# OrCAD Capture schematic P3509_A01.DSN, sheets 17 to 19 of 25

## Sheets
17 0008_PRE-REG 5V: size Custom
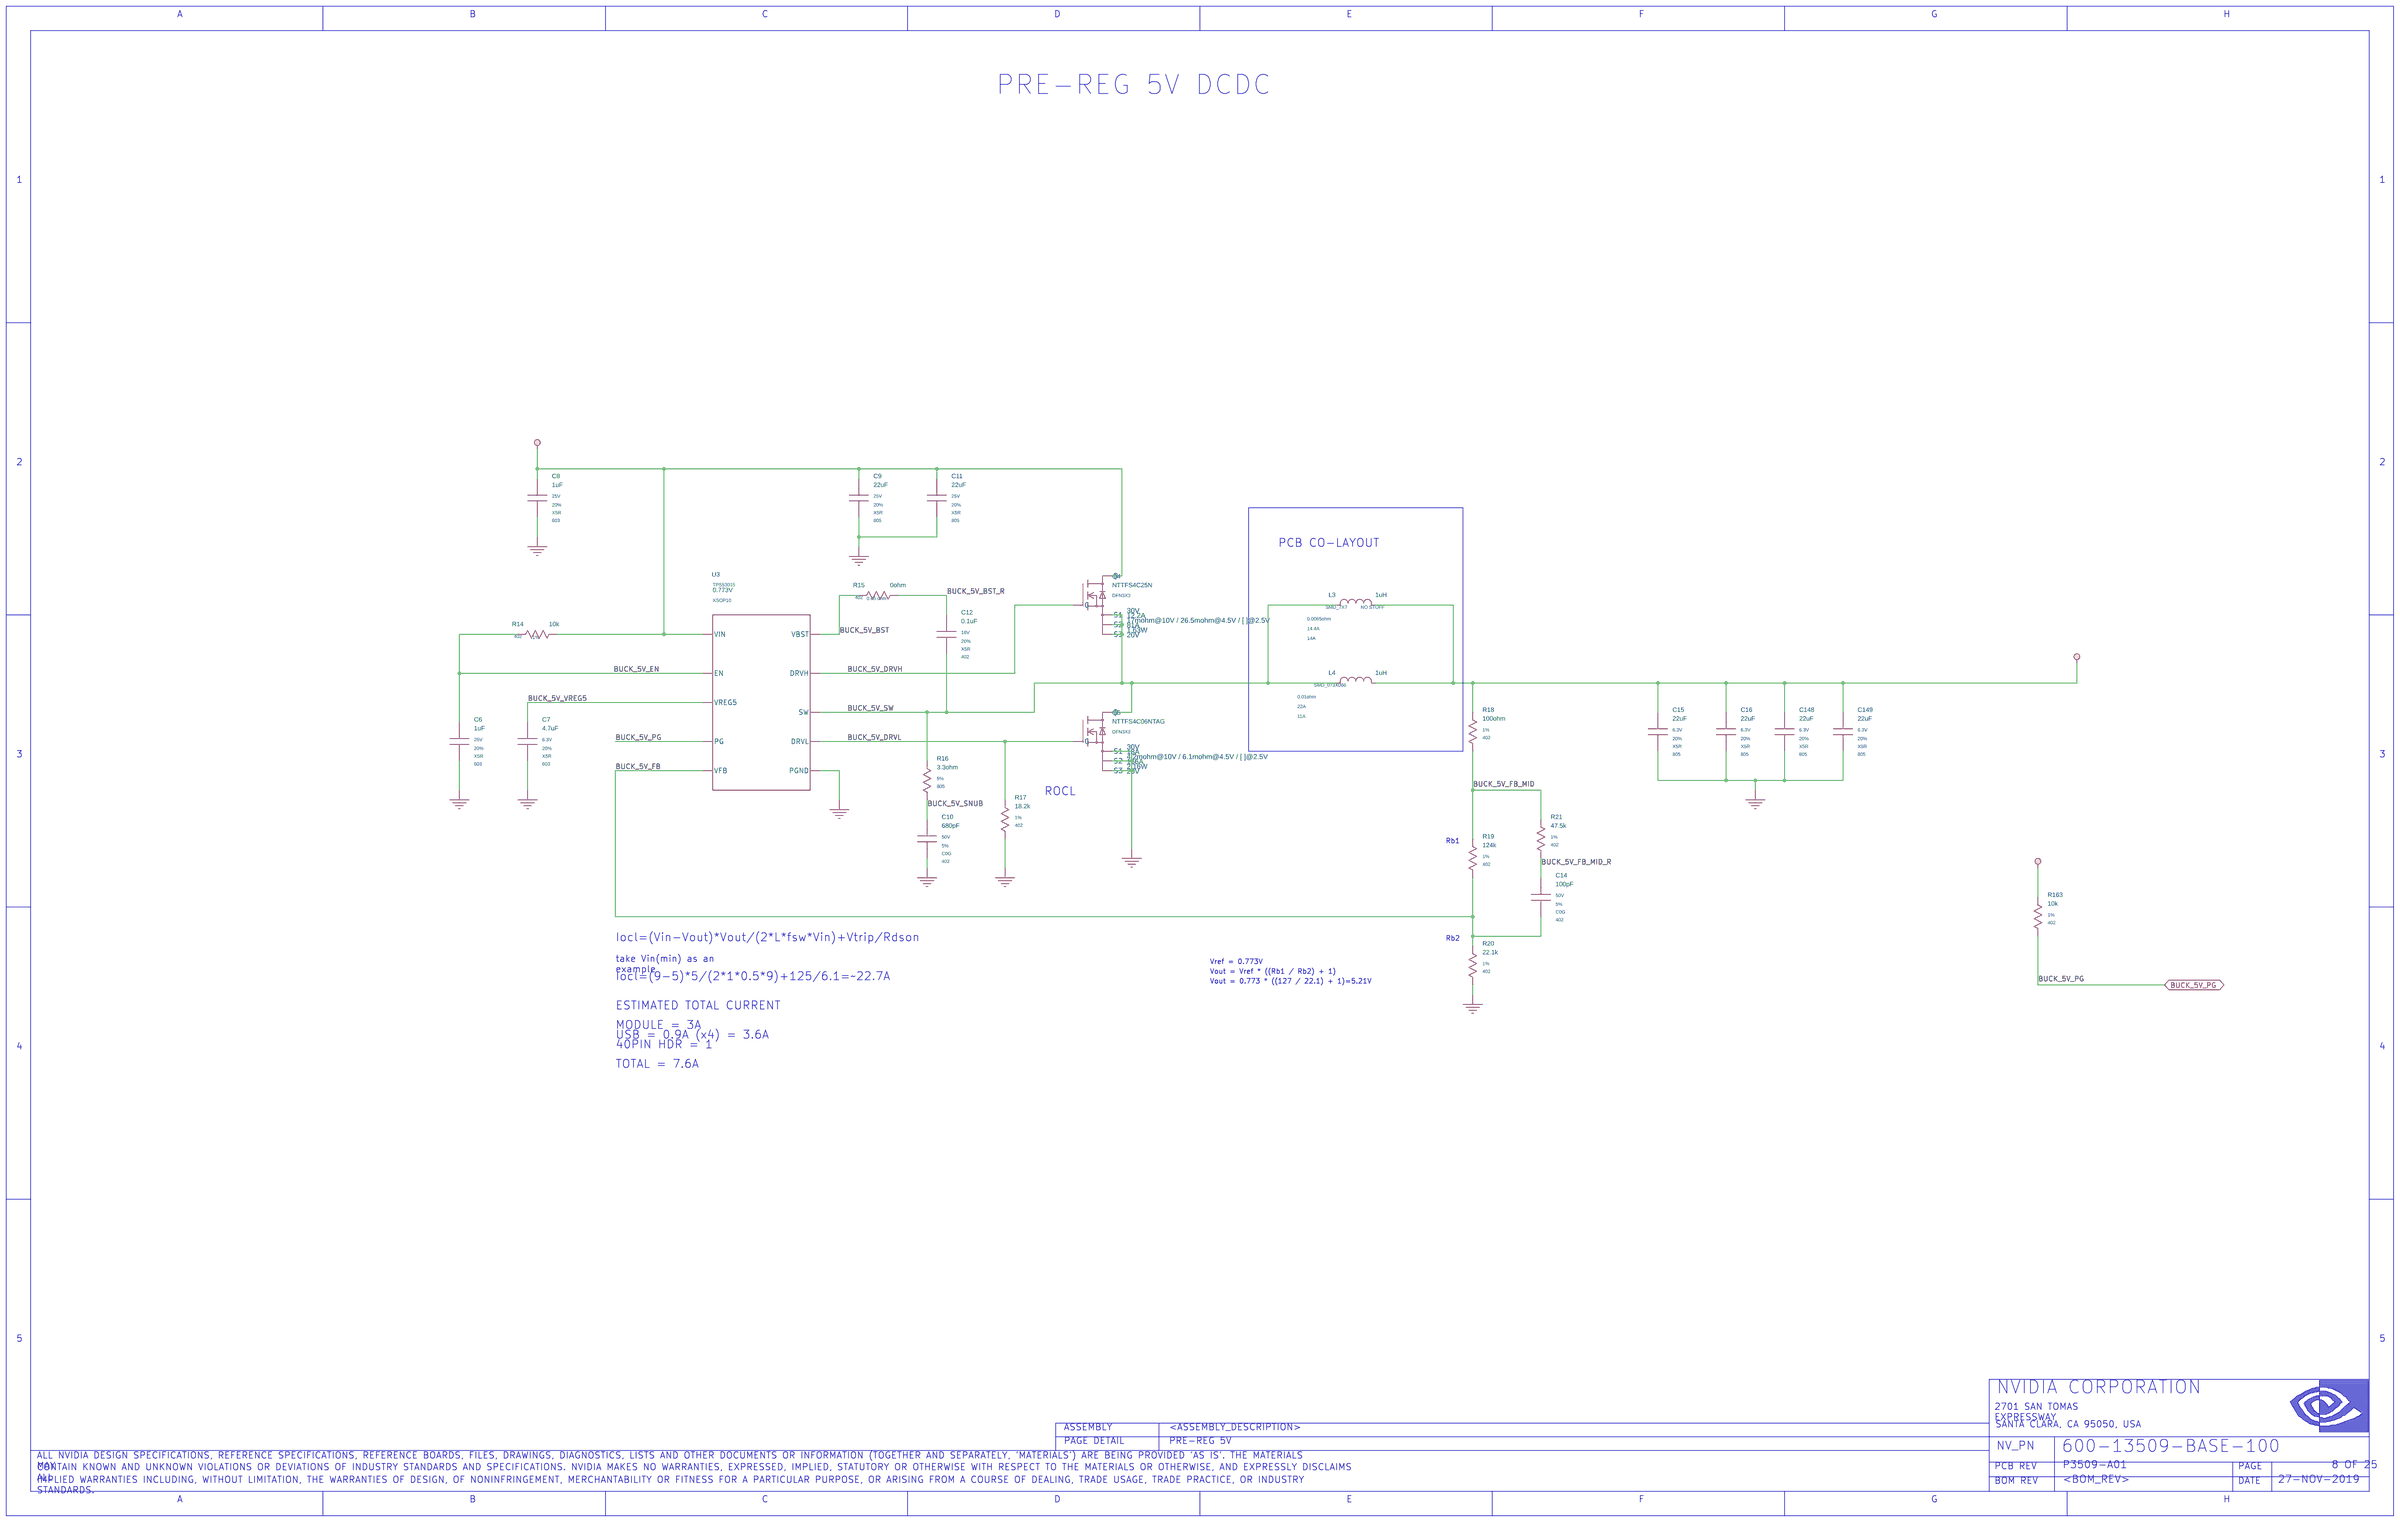
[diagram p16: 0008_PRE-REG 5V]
18 0007_DC_JACK: size Custom
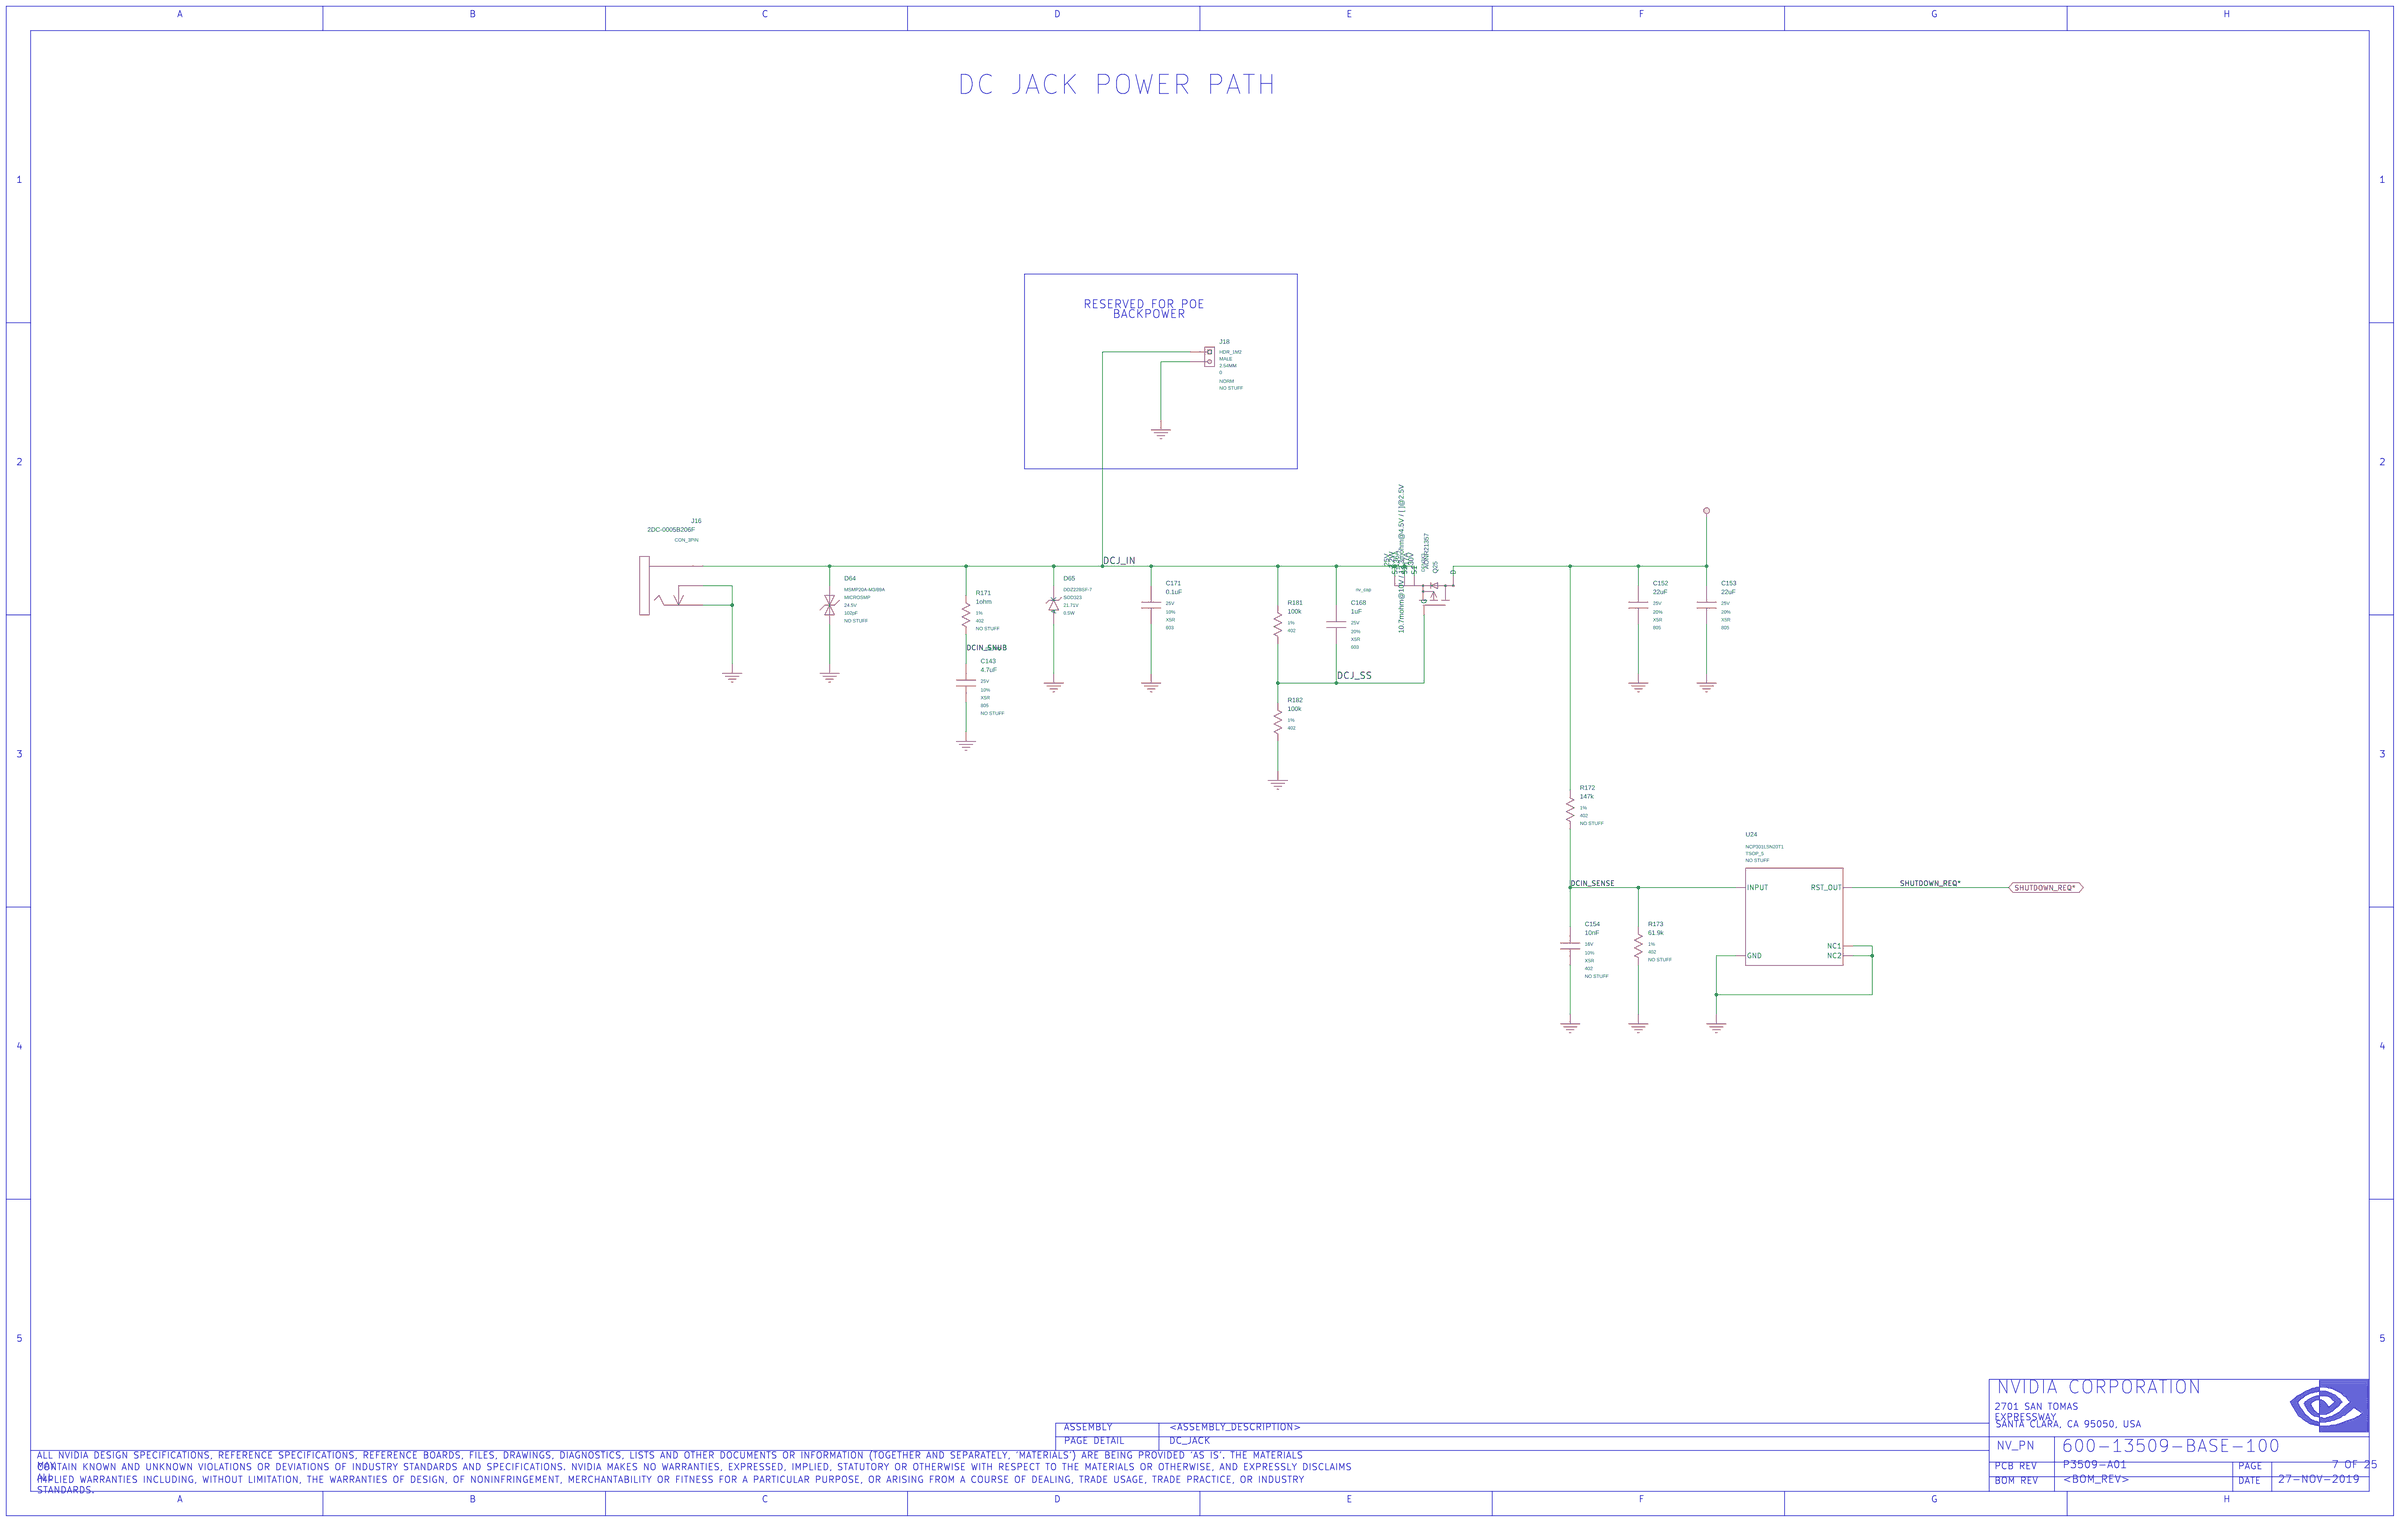
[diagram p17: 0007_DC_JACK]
19 0006_SODIMM Connector 3_3: size Custom
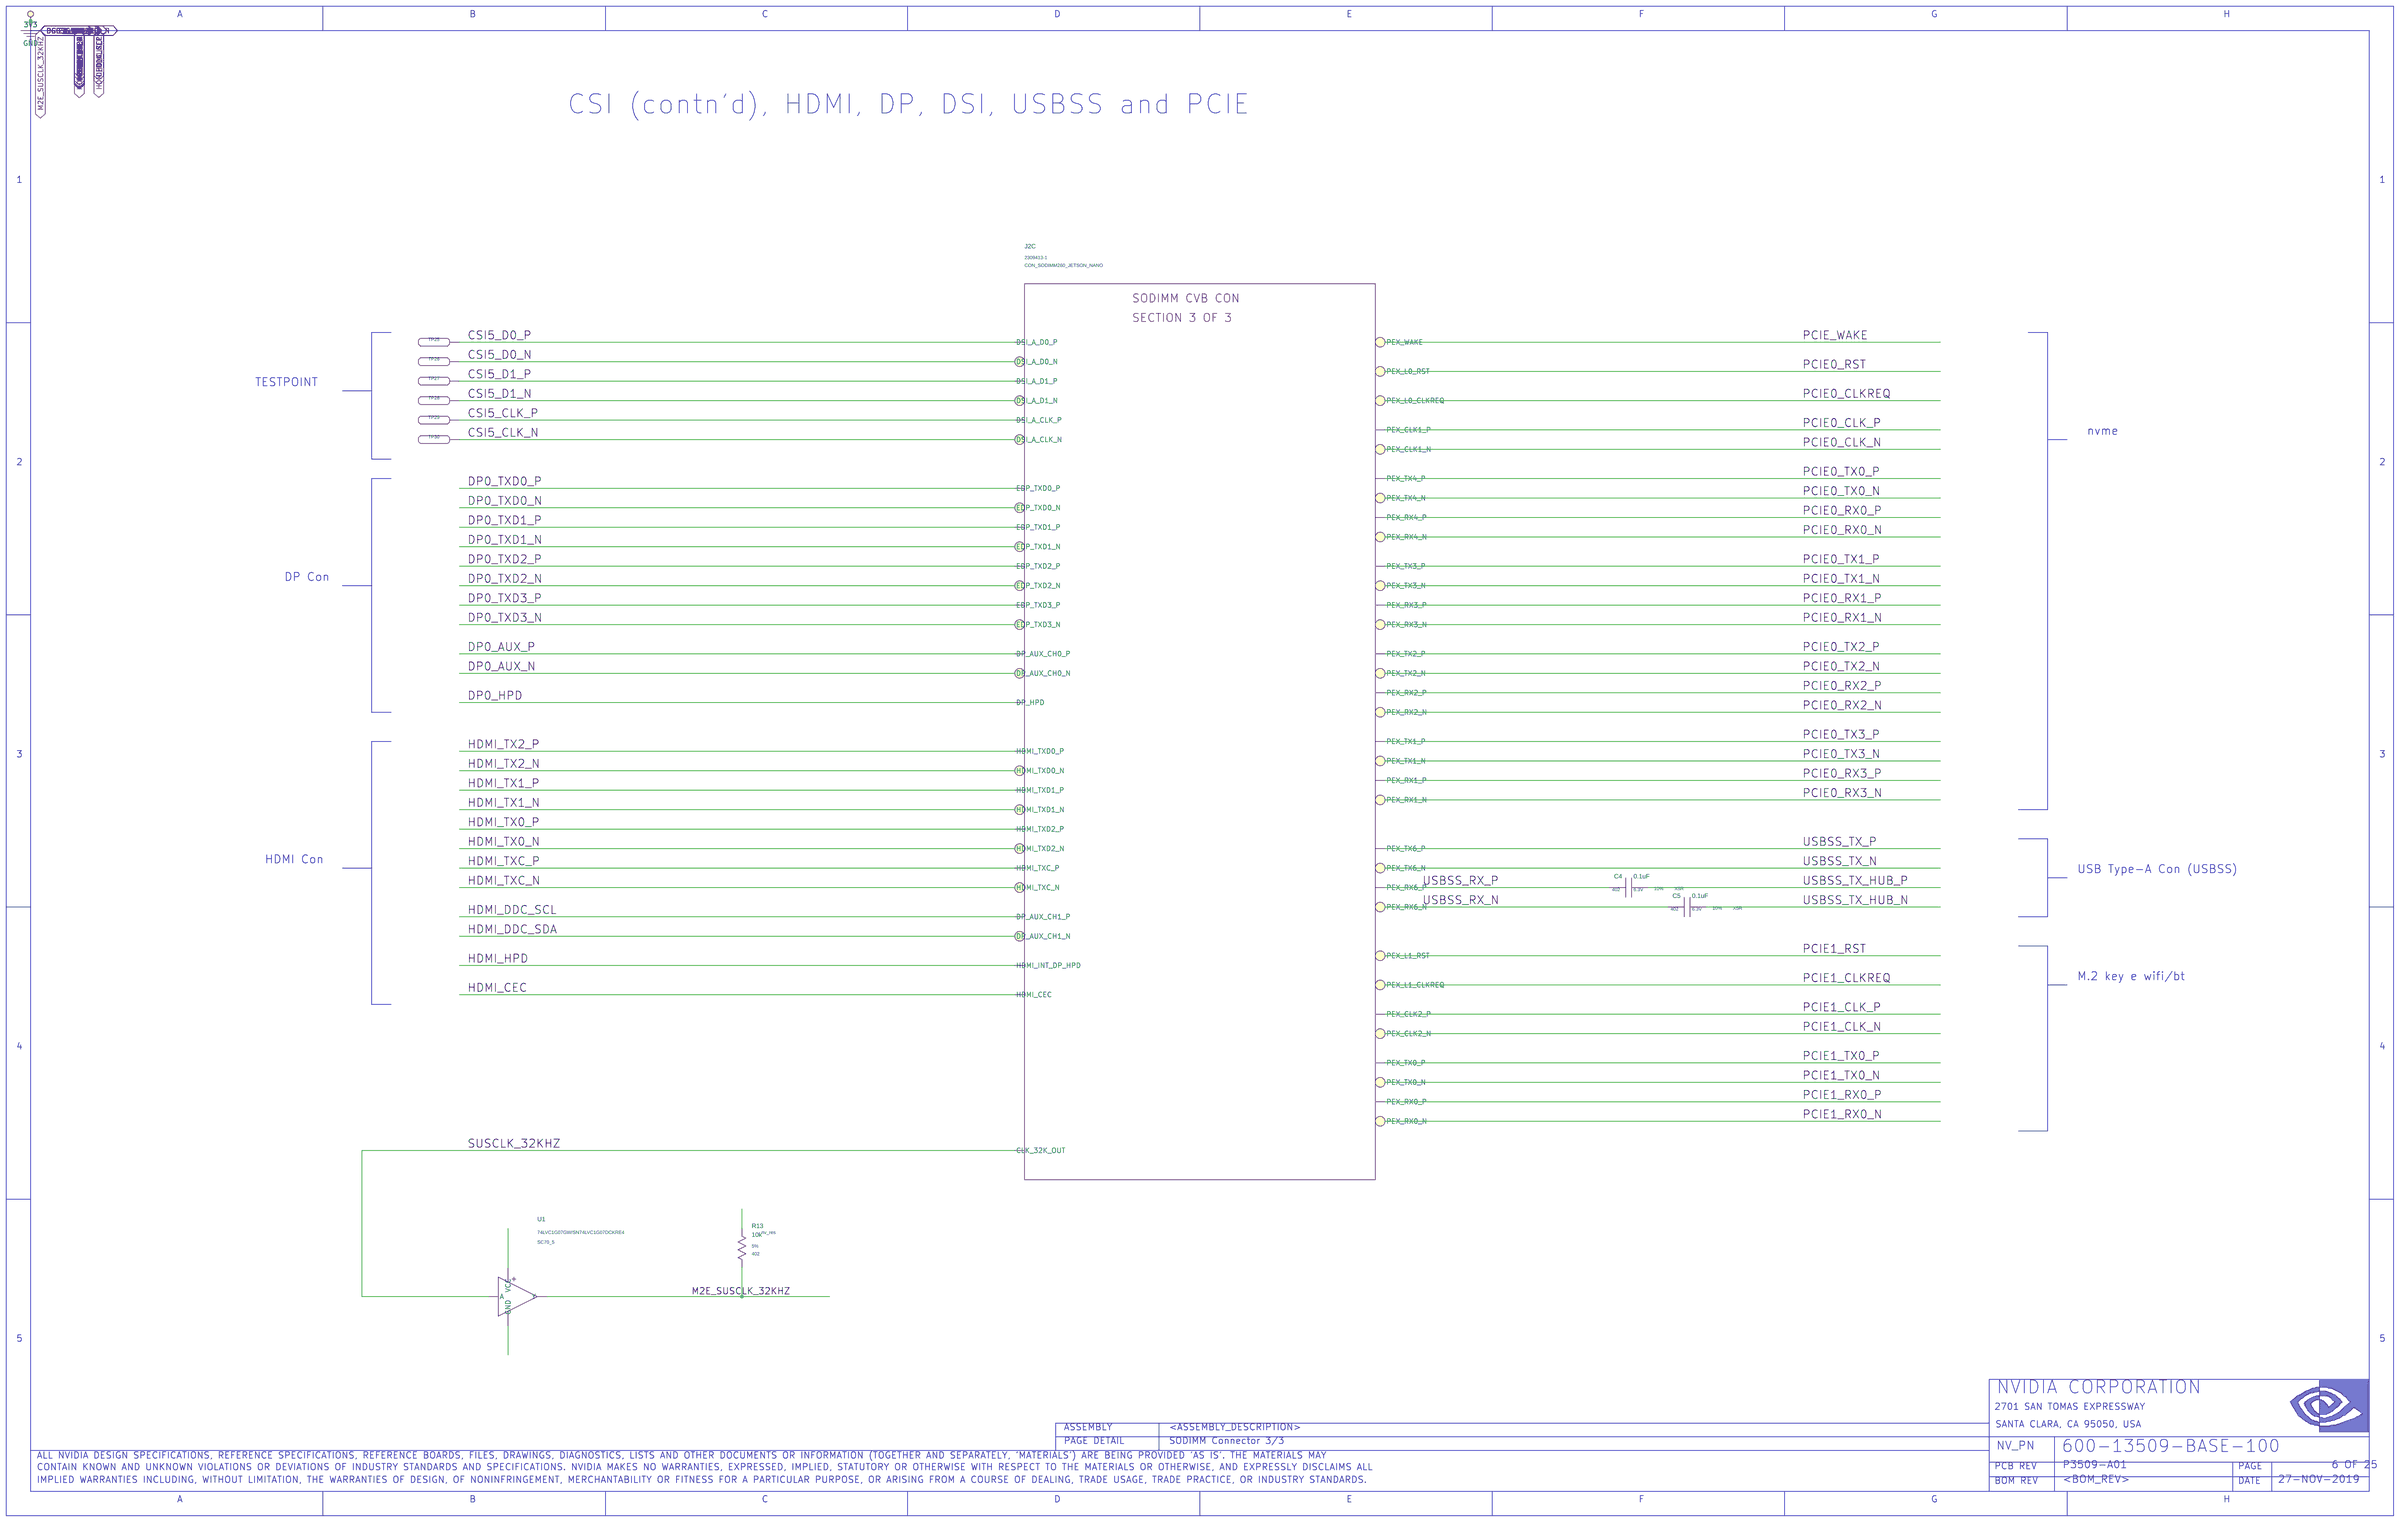
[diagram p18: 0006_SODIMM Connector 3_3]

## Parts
sheet 0005_SODIMM Connector 2_3
J2  CON_SODIMM_260  [CON_SODIMM_260_SMT_RA_F_P005]  (sections A,B,C)
sheet 0006_SODIMM Connector 3_3
C4  0.1uF  [402]
C5  0.1uF  [402]
R13  10k  [402]
TP25  LABTESTPOINT  [LTPB071C125D045C025P]
TP26  LABTESTPOINT  [LTPB071C125D045C025P]
TP27  LABTESTPOINT  [LTPB071C125D045C025P]
TP28  LABTESTPOINT  [LTPB071C125D045C025P]
TP29  LABTESTPOINT  [LTPB071C125D045C025P]
TP30  LABTESTPOINT  [LTPB071C125D045C025P]
U1  U_BUF_OD  [SC70_5]
sheet 0007_DC_JACK
C143  4.7uF  [805]
C152  22uF  [805]
C153  22uF  [805]
C154  10nF  [402]
C168  1uF  [603]
C171  0.1uF  [603]
D64  D_ESD  [DIODE_SMD_025X013]
D65  D_ZENER  [DIODE_SMD_SOD323_C]
J16  CON_PWR_JACK  [CON_PWR_003_TH_RA_145X090_C]
J18  HDR_1X2  [CON_HDR_001X002_TH_ST_M_P025]
Q25  Q_FET_P_ENH  [DFET_SMD_032X033]
R171  1ohm  [402]
R172  147k  [402]
R173  61.9k  [402]
R181  100k  [402]
R182  100k  [402]
U24  U_RST_MON  [SOT23_5]
sheet 0008_PRE-REG 5V
C6  1uF  [603]
C7  4.7uF  [603]
C8  1uF  [603]
C9  22uF  [805]
C10  680pF  [402]
C11  22uF  [805]
C12  0.1uF  [402]
C14  100pF  [402]
C15  22uF  [805]
C16  22uF  [805]
C148  22uF  [805]
C149  22uF  [805]
L3  1uH  [IND_NONRKO_SMD_071X065]
L4  1uH  [IND_NONRKO_SMD_073X066]
Q4  Q_FET_N_ENH  [MULTI_SMD_DFN08_SON08]
Q5  Q_FET_N_ENH  [MULTI_SMD_DFN08_SON08]
R14  10k  [402]
R15  0ohm  [402]
R16  3.3ohm  [805]
R17  18.2k  [402]
R18  100ohm  [402]
R19  124k  [402]
R20  22.1k  [402]
R21  47.5k  [402]
R163  10k  [402]
U3  0.773V  [XSOP10_P050_030X030]

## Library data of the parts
J2 = CON_SODIMM_260: ANGLE: 90; ASSEMBLY: CVB_CONN; CDS_LIB: electro_mechanic; CDS_PART_NAME: CON_SODIMM_260_CON_SODIMM260_JETSON_NANO-2309413-1,FEMALE,0.5MM,90,N/A,N/A,YES,NO,NO,25 V,0.5 A,080-1656-000; CDS_PHYS_PART_NAME: CON_SODIMM_260_CON_SODIMM260_JETSON_NANO-2309413-1,FEMALE,0.5MM,90,N/A,N/A,YES,NO,NO,25 V,0.5 A,080-1656-000-080-1656-000; CDS_SEC: 1; CaptureCellPackProp: CON_SODIMM_260A; DEVICE_TYPENAME: CON_SODIMM_260_CON_SODIMM260_JETSON_NANO-2309413-1FEMALE05MM90NANAYESNONO25V05A080-1656-000-080-1656-000; DRAWING: #NAME?; EMI_GROUND_TAB: NO; GENDER: FEMALE; LATCHING: YES; MAX_CURRENT: 0.5 A; MAX_VOLTAGE: 25 V; NV_NAME: 2309413-1; NV_PN: 080-1656-000; PACK_TYPE: CON_SODIMM260_JETSON_NANO; PATH: I62; PHYS_PAGE: 4; PITCH: 0.5mm; REFLOW: N/A; ROT: 0; SEC: 1; SHIELDED: NO; SHROUDED: N/A; VER: 5; XY: (-8650,3750)
C4 = C: ASSEMBLY: CVB_CONN; CDS_LIB: discrete; CDS_PART_NAME: C_0402-0.1UF,X5R,10%,6.3V,039-0007-000; CDS_PHYS_PART_NAME: C_0402-0.1UF,X5R,10%,6.3V,039-0007-000-0.1UF,039-0007-000; CDS_SEC: 1; DEVICE_TYPENAME: C_0402-01UFX5R1063V039-0007-000-01UF039-0007-000; DRAWING: #NAME?; MAT: X5R; MAX_VOLTAGE: 6.3V; NV_PN: 039-0007-000; PATH: I36; PHYS_PAGE: 6; ROT: 0; SEC: 1; SIGNAL_MODEL: nv_cap; TOL: 10%; VER: 2; XY: (-3800,3100)
C5 = C: ASSEMBLY: CVB_CONN; CDS_LIB: discrete; CDS_PART_NAME: C_0402-0.1UF,X5R,10%,6.3V,039-0007-000; CDS_PHYS_PART_NAME: C_0402-0.1UF,X5R,10%,6.3V,039-0007-000-0.1UF,039-0007-000; CDS_SEC: 1; DEVICE_TYPENAME: C_0402-01UFX5R1063V039-0007-000-01UF039-0007-000; DRAWING: #NAME?; MAT: X5R; MAX_VOLTAGE: 6.3V; NV_PN: 039-0007-000; PATH: I34; PHYS_PAGE: 6; ROT: 0; SEC: 1; SIGNAL_MODEL: nv_cap; TOL: 10%; VER: 2; XY: (-3500,3000)
R13 = R: ASSEMBLY: M2_WIFIBT; CDS_LIB: discrete; CDS_PART_NAME: R_0402-10K,5 %,62.5MW,195-0486-000; CDS_PHYS_PART_NAME: R_0402-10K,5 %,62.5MW,195-0486-000-10K,195-0486-000; CDS_SEC: 1; DEVICE_TYPENAME: R_0402-10K5625MW195-0486-000-10K195-0486-000; DRAWING: #NAME?; MAX_WATTAGE: 62.5mW; NV_PN: 195-0486-000; PATH: I87; PHYS_PAGE: 6; ROT: 0; SEC: 1; SIGNAL_MODEL: nv_res; TOL: 5%; VER: 2; XY: (-8350,1250)
TP25 = LABTESTPOINT#1: CDS_LIB: electro_mechanic; CDS_PART_NAME: LABTESTPOINT_PIN-LTPB071C125; CDS_PHYS_PART_NAME: LABTESTPOINT_PIN-LTPB071C125; CDS_SEC: 1; DEVICE_TYPENAME: LABTESTPOINT_PIN-LTPB071C125; DRAWING: #NAME?; NV_NAME: LTPB071C125; PACK_TYPE: PIN; PATH: I91; PHYS_PAGE: 6; ROT: 0; SEC: 1; VER: 1; XY: (-9850,5900)
TP26 = LABTESTPOINT#1: CDS_LIB: electro_mechanic; CDS_PART_NAME: LABTESTPOINT_PIN-LTPB071C125; CDS_PHYS_PART_NAME: LABTESTPOINT_PIN-LTPB071C125; CDS_SEC: 1; DEVICE_TYPENAME: LABTESTPOINT_PIN-LTPB071C125; DRAWING: #NAME?; NV_NAME: LTPB071C125; PACK_TYPE: PIN; PATH: I92; PHYS_PAGE: 6; ROT: 0; SEC: 1; VER: 1; XY: (-9850,5800)
TP27 = LABTESTPOINT#1: CDS_LIB: electro_mechanic; CDS_PART_NAME: LABTESTPOINT_PIN-LTPB071C125; CDS_PHYS_PART_NAME: LABTESTPOINT_PIN-LTPB071C125; CDS_SEC: 1; DEVICE_TYPENAME: LABTESTPOINT_PIN-LTPB071C125; DRAWING: #NAME?; NV_NAME: LTPB071C125; PACK_TYPE: PIN; PATH: I93; PHYS_PAGE: 6; ROT: 0; SEC: 1; VER: 1; XY: (-9850,5700)
TP28 = LABTESTPOINT#1: CDS_LIB: electro_mechanic; CDS_PART_NAME: LABTESTPOINT_PIN-LTPB071C125; CDS_PHYS_PART_NAME: LABTESTPOINT_PIN-LTPB071C125; CDS_SEC: 1; DEVICE_TYPENAME: LABTESTPOINT_PIN-LTPB071C125; DRAWING: #NAME?; NV_NAME: LTPB071C125; PACK_TYPE: PIN; PATH: I94; PHYS_PAGE: 6; ROT: 0; SEC: 1; VER: 1; XY: (-9850,5600)
TP29 = LABTESTPOINT#1: CDS_LIB: electro_mechanic; CDS_PART_NAME: LABTESTPOINT_PIN-LTPB071C125; CDS_PHYS_PART_NAME: LABTESTPOINT_PIN-LTPB071C125; CDS_SEC: 1; DEVICE_TYPENAME: LABTESTPOINT_PIN-LTPB071C125; DRAWING: #NAME?; NV_NAME: LTPB071C125; PACK_TYPE: PIN; PATH: I95; PHYS_PAGE: 6; ROT: 0; SEC: 1; VER: 1; XY: (-9850,5500)
TP30 = LABTESTPOINT#1: CDS_LIB: electro_mechanic; CDS_PART_NAME: LABTESTPOINT_PIN-LTPB071C125; CDS_PHYS_PART_NAME: LABTESTPOINT_PIN-LTPB071C125; CDS_SEC: 1; DEVICE_TYPENAME: LABTESTPOINT_PIN-LTPB071C125; DRAWING: #NAME?; NV_NAME: LTPB071C125; PACK_TYPE: PIN; PATH: I96; PHYS_PAGE: 6; ROT: 0; SEC: 1; VER: 1; XY: (-9850,5400)
U1 = U_BUF_OD: ASSEMBLY: M2_WIFIBT; CDS_LIB: logic; CDS_PART_NAME: U_BUF_OD_SC70_5-74LVC1G07GW/SN74LVC1G07DCKRE4,BUFFER - OPEN DRAIN,115-0138-000; CDS_PHYS_PART_NAME: U_BUF_OD_SC70_5-74LVC1G07GW/SN74LVC1G07DCKRE4,BUFFER - OPEN DRAIN,115-0138-000-115-0138-000; CDS_SEC: 1; DEVICE_TYPENAME: U_BUF_OD_SC70_5-74LVC1G07GWSN74LVC1G07DCKRE4BUFFER-OPENDRAIN115-0138-000-115-0138-000; DRAWING: #NAME?; FUNCTION: Buffer - Open Drain; NV_NAME: 74LVC1G07GW/SN74LVC1G07DCKRE4; NV_PN: 115-0138-000; PATH: I85; PHYS_PAGE: 6; ROT: 0; SEC: 1; VER: 1; XY: (-9500,1000)
C143 = C#1_v2: ASSEMBLY: DCJACK; CDS_LIB: discrete; CDS_PART_NAME: C_0805-4.7UF,X5R,10%,25V,032-1141-000; CDS_PHYS_PART_NAME: C_0805-4.7UF,X5R,10%,25V,032-1141-000-032-1141-000,4.7UF; CDS_SEC: 1; CHIPS_PART_NAME: C; DEVICE_TYPENAME: C_0805-47UFX5R1025V032-1141-000-032-1141-00047UF; DRAWING: #NAME?; IMPLEMENTATION_TYPE: X^@REFDES  %1    %2   @NV_PN; MAT: X5R; MAX_VOLTAGE: 25V; NV_PN: 032-1141-000; PATH: I29; PHYS_PAGE: 7; PSPICETEMPLATE: Pspice Model; ROT: 0; SEC: 1; SIGNAL_MODEL: nv_cap; SKU: NO STUFF; TOL: 10%; VER: 1; XY: (-7200,4150)
C152 = C#1_v2: ASSEMBLY: DCJACK; CDS_LIB: discrete; CDS_PART_NAME: C_0805-22UF,X5R,20%,25V,032-1308-000; CDS_PHYS_PART_NAME: C_0805-22UF,X5R,20%,25V,032-1308-000-032-1308-000,22UF; CDS_SEC: 1; CHIPS_PART_NAME: C; DEVICE_TYPENAME: C_0805-22UFX5R2025V032-1308-000-032-1308-00022UF; DRAWING: #NAME?; MAT: X5R; MAX_VOLTAGE: 25V; NV_PN: 032-1308-000; PATH: I38; PHYS_PAGE: 7; ROT: 0; SEC: 1; SIGNAL_MODEL: nv_cap; TOL: 20%; VER: 1; XY: (-3750,4550)
C153 = C#1_v2: ASSEMBLY: DCJACK; CDS_LIB: discrete; CDS_PART_NAME: C_0805-22UF,X5R,20%,25V,032-1308-000; CDS_PHYS_PART_NAME: C_0805-22UF,X5R,20%,25V,032-1308-000-032-1308-000,22UF; CDS_SEC: 1; CHIPS_PART_NAME: C; DEVICE_TYPENAME: C_0805-22UFX5R2025V032-1308-000-032-1308-00022UF; DRAWING: #NAME?; MAT: X5R; MAX_VOLTAGE: 25V; NV_PN: 032-1308-000; PATH: I37; PHYS_PAGE: 7; ROT: 0; SEC: 1; SIGNAL_MODEL: nv_cap; TOL: 20%; VER: 1; XY: (-3400,4550)
C154 = C#1_v2: ASSEMBLY: DCJACK; CDS_LIB: discrete; CDS_PART_NAME: C_0402-10NF,X5R,10%,16V,039-0024-000; CDS_PHYS_PART_NAME: C_0402-10NF,X5R,10%,16V,039-0024-000-039-0024-000,10NF; CDS_SEC: 1; CHIPS_PART_NAME: C; DEVICE_TYPENAME: C_0402-10NFX5R1016V039-0024-000-039-0024-00010NF; DRAWING: #NAME?; MAT: X5R; MAX_VOLTAGE: 16V; NV_PN: 039-0024-000; PATH: I51; PHYS_PAGE: 7; ROT: 0; SEC: 1; SKU: NO STUFF; TOL: 10%; VER: 1; XY: (-4100,2800)
C168 = C#1_v2: ASSEMBLY: DCJACK; CDS_LIB: discrete; CDS_PART_NAME: C_0603-1UF,X5R,20%,25V,032-0882-000; CDS_PHYS_PART_NAME: C_0603-1UF,X5R,20%,25V,032-0882-000-032-0882-000,1UF; CDS_SEC: 1; CHIPS_PART_NAME: C; DEVICE_TYPENAME: C_0603-1UFX5R2025V032-0882-000-032-0882-0001UF; DRAWING: #NAME?; IMPLEMENTATION_TYPE: X^@REFDES  %1    %2   @NV_PN; MAT: X5R; MAX_VOLTAGE: 25V; NV_PN: 032-0882-000; PATH: I59; PHYS_PAGE: 7; PSPICETEMPLATE: Pspice Model; ROT: 0; SEC: 1; SIGNAL_MODEL: nv_cap; TOL: 20%; VER: 1; XY: (-5300,4450)
C171 = C#1_v2: ASSEMBLY: DCJACK; CDS_LIB: discrete; CDS_PART_NAME: C_0603-0.1UF,X5R,10%,25V,039-0044-000; CDS_PHYS_PART_NAME: C_0603-0.1UF,X5R,10%,25V,039-0044-000-0.1UF,039-0044-000; CDS_SEC: 1; CHIPS_PART_NAME: C; DEVICE_TYPENAME: C_0603-01UFX5R1025V039-0044-000-01UF039-0044-000; DRAWING: #NAME?; MAT: X5R; MAX_VOLTAGE: 25V; NV_PN: 039-0044-000; PATH: I63; PHYS_PAGE: 7; ROT: 0; SEC: 1; TOL: 10%; VER: 1; XY: (-6250,4550)
D64 = D_ESD: ASSEMBLY: DCJACK; BREAKDOWN_VOLTAGE_MIN_TYP: 22.2V; CAPACITANCE_MAX_TYP: 102pF; CDS_LIB: discrete; CDS_PART_NAME: D_ESD_MICROSMP-MSMP20A-M3/89A,1 LINE,UNI-DIRECTIONAL,24.5V,1UA,22.2V,42.8V@23.4A,102PF,090-0378-000; CDS_PHYS_PART_NAME: D_ESD_MICROSMP-MSMP20A-M3/89A,1 LINE,UNI-DIRECTIONAL,24.5V,1UA,22.2V,42.8V@23.4A,102PF,090-0378-000-090-0378-000; CDS_SEC: 1; CLAMPING_VOLTAGE: 42.8V@23.4A; CONFIGURATION: 1 Line; DEVICE_TYPENAME: D_ESD_MICROSMP-MSMP20A-M389A1LINEUNI-DIRECTIONAL245V1UA222V428V234A102PF090-0378-000-090-0378-000; DRAWING: #NAME?; MAX_REVERSE_LEAKAGE_CURRENT: 1uA; MAX_REVERSE_VOLTAGE: 24.5V; NV_NAME: MSMP20A-M3/89A; NV_PN: 090-0378-000; PACK_TYPE: MICROSMP; PATH: I33; PHYS_PAGE: 7; POLARITY: Uni-Directional; ROT: 0; SEC: 1; SKU: NO STUFF; VER: 2; XY: (-7900,4550)
D65 = D_ZENER: ASSEMBLY: DCJACK; CDS_LIB: discrete; CDS_PART_NAME: D_ZENER_SOD323-DDZ22BSF-7,21.71V,5MA,0.9V@10MA,0.5W,090-0377-000; CDS_PHYS_PART_NAME: D_ZENER_SOD323-DDZ22BSF-7,21.71V,5MA,0.9V@10MA,0.5W,090-0377-000-090-0377-000; CDS_SEC: 1; CONTINUOUS_CURRENT: 0.5W; DEVICE_TYPENAME: D_ZENER_SOD323-DDZ22BSF-72171V5MA09V10MA05W090-0377-000-090-0377-000; DRAWING: #NAME?; FORWARD_VOLTAGE: 0.9V@10mA; MAX_CURRENT: 5mA; MAX_VOLTAGE: 21.71V; NV_NAME: DDZ22BSF-7; NV_PN: 090-0377-000; PACK_TYPE: SOD323; PATH: I34; PHYS_PAGE: 7; ROT: 0; SEC: 1; VER: 2; XY: (-6750,4550)
J16 = CON_PWR_JACK: ANGLE: 90; ASSEMBLY: DCJACK; CDS_LIB: electro_mechanic; CDS_PART_NAME: CON_PWR_JACK_CON_3PIN-2DC-0005B206F,FEMALE,N/A,90,NO,YES,N/A,N/A,NO,24 V,5 A,064-0437-000; CDS_PHYS_PART_NAME: CON_PWR_JACK_CON_3PIN-2DC-0005B206F,FEMALE,N/A,90,NO,YES,N/A,N/A,NO,24 V,5 A,064-0437-000-064-0437-000; CDS_SEC: 1; DEVICE_TYPENAME: CON_PWR_JACK_CON_3PIN-2DC-0005B206FFEMALENA90NOYESNANANO24V5A064-0437-000-064-0437-000; DRAWING: #NAME?; EMI_GROUND_TAB: N/A; GENDER: FEMALE; LATCHING: N/A; MAX_CURRENT: 5:00 AM; MAX_VOLTAGE: 24 V; NV_NAME: 2DC-0005B206F; NV_PN: 064-0437-000; PACK_TYPE: CON_3PIN; PATH: I31; PHYS_PAGE: 7; PITCH: N/A; REFLOW: NO; ROT: 2; SEC: 1; SEC_TYPE: CON_3PIN; SHIELDED: NO; SHROUDED: YES; VER: 1; XY: (-8850,4750)
J18 = HDR_1X2: ANGLE: 0; ASSEMBLY: DCJACK; CDS_LIB: electro_mechanic; CDS_PART_NAME: HDR_1X2_NORM-HDR_1M2,MALE,2.54MM,0,NO,NO,NO,250V,3A,074-0117-000; CDS_PHYS_PART_NAME: HDR_1X2_NORM-HDR_1M2,MALE,2.54MM,0,NO,NO,NO,250V,3A,074-0117-000-074-0117-000; CDS_SEC: 1; DEVICE_TYPENAME: HDR_1X2_NORM-HDR_1M2MALE254MM0NONONO250V3A074-0117-000-074-0117-000; DRAWING: #NAME?; GENDER: MALE; LATCHING: NO; MAX_CURRENT: 3A; MAX_VOLTAGE: 250V; NV_NAME: HDR_1M2; NV_PN: 074-0117-000; PACK_TYPE: NORM; PATH: I61; PHYS_PAGE: 7; PITCH: 2.54MM; REFLOW: NO; ROT: 0; SEC: 1; SHROUDED: NO; SKU: NO STUFF; VER: 1; XY: (-5950,5850)
Q25 = Q_FET_P_ENH: ASSEMBLY: DCJACK; CDS_LIB: discrete; CDS_PART_NAME: Q_FET_P_ENH_DFN3X3-AONR21357,-30V,10.7MOHM@10V / 12.3MOHM@4.5V / [ ]@2.5V,-17A,-136A,25V,3.2W,70NC@10V / 35NC@4.5V / [ ]@2.5V,A; CDS_PHYS_PART_NAME: Q_FET_P_ENH_DFN3X3-AONR21357,-30V,10.7MOHM@10V / 12.3MOHM@4.5V / [ ]@2.5V,-17A,-136A,25V,3.2W,70NC@10V / 35NC@4.5V / [ ]@2.5V,B; CDS_SEC: 1; CONTINUOUS_CURRENT: -17A; DEVICE_TYPENAME: Q_FET_P_ENH_DFN3X3-AONR21357-30V107MOHM10V123MOHM45V25V-17A-136A25V32W70NC10V35NC45V25VB; DRAWING: #NAME?; MAX_CURRENT: -136A; MAX_VOLTAGE: -30V; MAX_WATTAGE: 3.2W; NV_NAME: AONR21357; NV_PN: 300-1070-000; PACK_TYPE: DFN3X3; PATH: I56; PHYS_PAGE: 7; Q_G: 70nC@10V / 35nC@4.5V / [ ]@2.5V; ROT: 7; R_DS_ON: 10.7mohm@10V / 12.3mohm@4.5V / [ ]@2.5V; SEC: 1; VER: 8; V_BE_GS: 25V; XY: (-4800,4600)
R171 = R: ASSEMBLY: DCJACK; CDS_LIB: discrete; CDS_PART_NAME: R_0402-1OHM,1 %,62.5MW,195-2682-000; CDS_PHYS_PART_NAME: R_0402-1OHM,1 %,62.5MW,195-2682-000-195-2682-000,1OHM; CDS_SEC: 1; DEVICE_TYPENAME: R_0402-1OHM1625MW195-2682-000-195-2682-0001OHM; DRAWING: #NAME?; MAX_WATTAGE: 62.5mW; NV_PN: 195-2682-000; PATH: I41; PHYS_PAGE: 7; ROT: 0; SEC: 1; SKU: NO STUFF; TOL: 1%; VER: 2; XY: (-7200,4500)
R172 = R: ASSEMBLY: DCJACK; CDS_LIB: discrete; CDS_PART_NAME: R_0402-147K,1 %,62.5MW,195-0086-000; CDS_PHYS_PART_NAME: R_0402-147K,1 %,62.5MW,195-0086-000-147K,195-0086-000; CDS_SEC: 1; DEVICE_TYPENAME: R_0402-147K1625MW195-0086-000-147K195-0086-000; DRAWING: #NAME?; MAX_WATTAGE: 62.5mW; NV_PN: 195-0086-000; PATH: I53; PHYS_PAGE: 7; ROT: 0; SEC: 1; SKU: NO STUFF; TOL: 1%; VER: 2; XY: (-4100,3500)
R173 = R: ASSEMBLY: DCJACK; CDS_LIB: discrete; CDS_PART_NAME: R_0402-61.9K,1 %,62.5MW,195-0385-000; CDS_PHYS_PART_NAME: R_0402-61.9K,1 %,62.5MW,195-0385-000-195-0385-000,61.9K; CDS_SEC: 1; DEVICE_TYPENAME: R_0402-619K1625MW195-0385-000-195-0385-000619K; DRAWING: #NAME?; MAX_WATTAGE: 62.5mW; NV_PN: 195-0385-000; PATH: I52; PHYS_PAGE: 7; ROT: 0; SEC: 1; SKU: NO STUFF; TOL: 1%; VER: 2; XY: (-3750,2800)
R181 = R: ASSEMBLY: DCJACK; CDS_LIB: discrete; CDS_PART_NAME: R_0402-100K,1 %,62.5MW,195-0005-000; CDS_PHYS_PART_NAME: R_0402-100K,1 %,62.5MW,195-0005-000-100K,195-0005-000; CDS_SEC: 1; DEVICE_TYPENAME: R_0402-100K1625MW195-0005-000-100K195-0005-000; DRAWING: #NAME?; MAX_WATTAGE: 62.5mW; NV_PN: 195-0005-000; PATH: I57; PHYS_PAGE: 7; ROT: 0; SEC: 1; TOL: 1%; VER: 2; XY: (-5600,4450)
R182 = R: ASSEMBLY: DCJACK; CDS_LIB: discrete; CDS_PART_NAME: R_0402-100K,1 %,62.5MW,195-0005-000; CDS_PHYS_PART_NAME: R_0402-100K,1 %,62.5MW,195-0005-000-100K,195-0005-000; CDS_SEC: 1; DEVICE_TYPENAME: R_0402-100K1625MW195-0005-000-100K195-0005-000; DRAWING: #NAME?; MAX_WATTAGE: 62.5mW; NV_PN: 195-0005-000; PATH: I58; PHYS_PAGE: 7; ROT: 0; SEC: 1; TOL: 1%; VER: 2; XY: (-5600,3950)
U24 = U_RST_MON: ASSEMBLY: DCJACK; CDS_LIB: digital; CDS_PART_NAME: U_RST_MON_TSOP_5-NCP301LSN20T1,VOLTAGE SUPERVISOR,115-2146-000; CDS_PHYS_PART_NAME: U_RST_MON_TSOP_5-NCP301LSN20T1,VOLTAGE SUPERVISOR,115-2146-000-115-2146-000; CDS_SEC: 1; DEVICE_TYPENAME: U_RST_MON_TSOP_5-NCP301LSN20T1VOLTAGESUPERVISOR115-2146-000-115-2146-000; DRAWING: #NAME?; NV_NAME: NCP301LSN20T1; NV_PN: 115-2146-000; PACK_TYPE: TSOP_5; PATH: I46; PHYS_PAGE: 7; ROT: 0; SEC: 1; SKU: NO STUFF; TYPE: Voltage Supervisor; VER: 6; XY: (-2950,2950)
C6 = C#1_v2: ASSEMBLY: PS_5V; CDS_LIB: discrete; CDS_PART_NAME: C_0603-1UF,X5R,20%,25V,032-0882-000; CDS_PHYS_PART_NAME: C_0603-1UF,X5R,20%,25V,032-0882-000-032-0882-000,1UF; CDS_SEC: 1; CHIPS_PART_NAME: C; DEVICE_TYPENAME: C_0603-1UFX5R2025V032-0882-000-032-0882-0001UF; DRAWING: #NAME?; MAT: X5R; MAX_VOLTAGE: 25V; NV_PN: 032-0882-000; PATH: I42; PHYS_PAGE: 8; ROT: 0; SEC: 1; SIGNAL_MODEL: nv_cap; TOL: 20%; VER: 1; XY: (-9800,3850)
C7 = C#1_v2: ASSEMBLY: PS_5V; CDS_LIB: discrete; CDS_PART_NAME: C_0603-4.7UF,X5R,20%,6.3V,032-0886-000; CDS_PHYS_PART_NAME: C_0603-4.7UF,X5R,20%,6.3V,032-0886-000-032-0886-000,4.7UF; CDS_SEC: 1; CHIPS_PART_NAME: C; DEVICE_TYPENAME: C_0603-47UFX5R2063V032-0886-000-032-0886-00047UF; DRAWING: #NAME?; ESL: N/A; ESR: N/A; MAT: X5R; MAX_VOLTAGE: 6.3V; NV_PN: 032-0886-000; PATH: I40; PHYS_PAGE: 8; ROT: 0; SEC: 1; SIGNAL_MODEL: nv_cap; TOL: 20%; VER: 1; XY: (-9450,3850)
C8 = C#1_v2: ASSEMBLY: PS_5V; CDS_LIB: discrete; CDS_PART_NAME: C_0603-1UF,X5R,20%,25V,032-0882-000; CDS_PHYS_PART_NAME: C_0603-1UF,X5R,20%,25V,032-0882-000-032-0882-000,1UF; CDS_SEC: 1; CHIPS_PART_NAME: C; DEVICE_TYPENAME: C_0603-1UFX5R2025V032-0882-000-032-0882-0001UF; DRAWING: #NAME?; MAT: X5R; MAX_VOLTAGE: 25V; NV_PN: 032-0882-000; PATH: I37; PHYS_PAGE: 8; ROT: 0; SEC: 1; SIGNAL_MODEL: nv_cap; TOL: 20%; VER: 1; XY: (-9400,5100)
C9 = C#1_v2: ASSEMBLY: PS_5V; CDS_LIB: discrete; CDS_PART_NAME: C_0805-22UF,X5R,20%,25V,032-1308-000; CDS_PHYS_PART_NAME: C_0805-22UF,X5R,20%,25V,032-1308-000-032-1308-000,22UF; CDS_SEC: 1; CHIPS_PART_NAME: C; DEVICE_TYPENAME: C_0805-22UFX5R2025V032-1308-000-032-1308-00022UF; DRAWING: #NAME?; MAT: X5R; MAX_VOLTAGE: 25V; NV_PN: 032-1308-000; PATH: I22; PHYS_PAGE: 8; ROT: 0; SEC: 1; SIGNAL_MODEL: nv_cap; TOL: 20%; VER: 1; XY: (-7750,5100)
C10 = C#1_v2: ASSEMBLY: PS_5V; CDS_LIB: discrete; CDS_PART_NAME: C_0402-680PF,C0G,5%,50V,035-0296-000; CDS_PHYS_PART_NAME: C_0402-680PF,C0G,5%,50V,035-0296-000-035-0296-000,680PF; CDS_SEC: 1; CHIPS_PART_NAME: C; DEVICE_TYPENAME: C_0402-680PFC0G550V035-0296-000-035-0296-000680PF; DRAWING: #NAME?; MAT: C0G; MAX_VOLTAGE: 50V; NV_PN: 035-0296-000; PATH: I28; PHYS_PAGE: 8; ROT: 0; SEC: 1; SIGNAL_MODEL: nv_cap; TOL: 5%; VER: 1; XY: (-7400,3350)
C11 = C#1_v2: ASSEMBLY: PS_5V; CDS_LIB: discrete; CDS_PART_NAME: C_0805-22UF,X5R,20%,25V,032-1308-000; CDS_PHYS_PART_NAME: C_0805-22UF,X5R,20%,25V,032-1308-000-032-1308-000,22UF; CDS_SEC: 1; CHIPS_PART_NAME: C; DEVICE_TYPENAME: C_0805-22UFX5R2025V032-1308-000-032-1308-00022UF; DRAWING: #NAME?; MAT: X5R; MAX_VOLTAGE: 25V; NV_PN: 032-1308-000; PATH: I21; PHYS_PAGE: 8; ROT: 0; SEC: 1; SIGNAL_MODEL: nv_cap; TOL: 20%; VER: 1; XY: (-7350,5100)
C12 = C#1_v2: ASSEMBLY: PS_5V; CDS_LIB: discrete; CDS_PART_NAME: C_0402-0.1UF,X5R,20%,16V,032-0877-000; CDS_PHYS_PART_NAME: C_0402-0.1UF,X5R,20%,16V,032-0877-000-0.1UF,032-0877-000; CDS_SEC: 1; CHIPS_PART_NAME: C; DEVICE_TYPENAME: C_0402-01UFX5R2016V032-0877-000-01UF032-0877-000; DRAWING: #NAME?; MAT: X5R; MAX_VOLTAGE: 16V; NV_PN: 032-0877-000; PATH: I24; PHYS_PAGE: 8; ROT: 0; SEC: 1; TOL: 20%; VER: 1; XY: (-7300,4400)
C14 = C#1_v2: ASSEMBLY: PS_5V; CDS_LIB: discrete; CDS_PART_NAME: C_0402-100PF,C0G,5%,50V,035-0012-000; CDS_PHYS_PART_NAME: C_0402-100PF,C0G,5%,50V,035-0012-000-035-0012-000,100PF; CDS_SEC: 1; CHIPS_PART_NAME: C; DEVICE_TYPENAME: C_0402-100PFC0G550V035-0012-000-035-0012-000100PF; DRAWING: #NAME?; MAT: C0G; MAX_VOLTAGE: 50V; NV_PN: 035-0012-000; PATH: I2; PHYS_PAGE: 8; ROT: 0; SEC: 1; SIGNAL_MODEL: nv_cap; TOL: 5%; VER: 1; XY: (-4250,3050)
C15 = C#1_v2: ASSEMBLY: PS_5V; CDS_LIB: discrete; CDS_PART_NAME: C_0805-22UF,X5R,20%,6.3V,039-0127-000; CDS_PHYS_PART_NAME: C_0805-22UF,X5R,20%,6.3V,039-0127-000-039-0127-000,22UF; CDS_SEC: 1; CHIPS_PART_NAME: C; DEVICE_TYPENAME: C_0805-22UFX5R2063V039-0127-000-039-0127-00022UF; DRAWING: #NAME?; MAT: X5R; MAX_VOLTAGE: 6.3V; NV_PN: 039-0127-000; PATH: I13; PHYS_PAGE: 8; ROT: 0; SEC: 1; SIGNAL_MODEL: nv_cap; TOL: 20%; VER: 1; XY: (-3650,3900)
C16 = C#1_v2: ASSEMBLY: PS_5V; CDS_LIB: discrete; CDS_PART_NAME: C_0805-22UF,X5R,20%,6.3V,039-0127-000; CDS_PHYS_PART_NAME: C_0805-22UF,X5R,20%,6.3V,039-0127-000-039-0127-000,22UF; CDS_SEC: 1; CHIPS_PART_NAME: C; DEVICE_TYPENAME: C_0805-22UFX5R2063V039-0127-000-039-0127-00022UF; DRAWING: #NAME?; MAT: X5R; MAX_VOLTAGE: 6.3V; NV_PN: 039-0127-000; PATH: I11; PHYS_PAGE: 8; ROT: 0; SEC: 1; SIGNAL_MODEL: nv_cap; TOL: 20%; VER: 1; XY: (-3300,3900)
C148 = C#1_v2: ASSEMBLY: PS_5V; CDS_LIB: discrete; CDS_PART_NAME: C_0805-22UF,X5R,20%,6.3V,039-0127-000; CDS_PHYS_PART_NAME: C_0805-22UF,X5R,20%,6.3V,039-0127-000-039-0127-000,22UF; CDS_SEC: 1; CHIPS_PART_NAME: C; DEVICE_TYPENAME: C_0805-22UFX5R2063V039-0127-000-039-0127-00022UF; DRAWING: #NAME?; MAT: X5R; MAX_VOLTAGE: 6.3V; NV_PN: 039-0127-000; PATH: I50; PHYS_PAGE: 8; ROT: 0; SEC: 1; SIGNAL_MODEL: nv_cap; TOL: 20%; VER: 1; XY: (-3000,3900)
C149 = C#1_v2: ASSEMBLY: PS_5V; CDS_LIB: discrete; CDS_PART_NAME: C_0805-22UF,X5R,20%,6.3V,039-0127-000; CDS_PHYS_PART_NAME: C_0805-22UF,X5R,20%,6.3V,039-0127-000-039-0127-000,22UF; CDS_SEC: 1; CHIPS_PART_NAME: C; DEVICE_TYPENAME: C_0805-22UFX5R2063V039-0127-000-039-0127-00022UF; DRAWING: #NAME?; MAT: X5R; MAX_VOLTAGE: 6.3V; NV_PN: 039-0127-000; PATH: I51; PHYS_PAGE: 8; ROT: 0; SEC: 1; SIGNAL_MODEL: nv_cap; TOL: 20%; VER: 1; XY: (-2700,3900)
L3 = L: ASSEMBLY: PS_5V; CDS_LIB: discrete; CDS_PART_NAME: L_SMD_7X7-1UH,IRON POWDER CORE,20%,14A,14.4A,0.0065OHM,0@0HZ,3MHZ,130-0996-000; CDS_PHYS_PART_NAME: L_SMD_7X7-1UH,IRON POWDER CORE,20%,14A,14.4A,0.0065OHM,0@0HZ,3MHZ,130-0996-000-130-0996-000,1UH; CDS_SEC: 1; CONTINUOUS_CURRENT: 14A; DC_RESISTANCE: 0.0065ohm; DEVICE_TYPENAME: L_SMD_7X7-1UHIRONPOWDERCORE2014A144A00065OHM00HZ3MHZ130-0996-000-130-0996-0001UH; DRAWING: #NAME?; MAT: Iron powder core; MAX_CURRENT: 14.4A; NV_PN: 130-0996-000; PACK_TYPE: SMD_7X7; PATH: I15; PHYS_PAGE: 8; Q: 0@0Hz; ROT: 0; SEC: 1; SELF_RESONANCE_FREQ: 3MHz; SIGNAL_MODEL: nv_ind; SKU: NO STUFF; TOL: 20%; VER: 1; XY: (-5200,4550)
L4 = L: ASSEMBLY: PS_5V; CDS_LIB: discrete; CDS_PART_NAME: L_SMD_073X066-1UH,CARBONYL POWDER,20%,11A,22A,0.01OHM,[ ]@[ ],[ ],130-0776-000; CDS_PHYS_PART_NAME: L_SMD_073X066-1UH,CARBONYL POWDER,20%,11A,22A,0.01OHM,[ ]@[ ],[ ],130-0776-000-130-0776-000,1UH; CDS_SEC: 1; CONTINUOUS_CURRENT: 11A; DC_RESISTANCE: 0.01ohm; DEVICE_TYPENAME: L_SMD_073X066-1UHCARBONYLPOWDER2011A22A001OHM130-0776-000-130-0776-0001UH; DRAWING: #NAME?; MAT: Carbonyl Powder; MAX_CURRENT: 22A; NV_PN: 130-0776-000; PACK_TYPE: SMD_073X066; PATH: I16; PHYS_PAGE: 8; Q: [ ]@[ ]; ROT: 0; SEC: 1; SELF_RESONANCE_FREQ: [ ]; SIGNAL_MODEL: nv_ind; TOL: 20%; VER: 1; XY: (-5200,4150)
Q4 = Q_FET_N_ENH#2: ASSEMBLY: PS_5V; CDS_LIB: discrete; CDS_PART_NAME: Q_FET_N_ENH_DFN3X3-NTTFS4C25N,30V,17MOHM@10V / 26.5MOHM@4.5V / [ ]@2.5V,12.2A,81A,20V,1.63W,10.3NC@10V / 5.1NC@4.5V / [ ]@2.5VA; CDS_PHYS_PART_NAME: Q_FET_N_ENH_DFN3X3-NTTFS4C25N,30V,17MOHM@10V / 26.5MOHM@4.5V / [ ]@2.5V,12.2A,81A,20V,1.63W,10.3NC@10V / 5.1NC@4.5V / [ ]@2.5VB; CDS_SEC: 1; CONTINUOUS_CURRENT: 12.2A; DEVICE_TYPENAME: Q_FET_N_ENH_DFN3X3-NTTFS4C25N30V17MOHM10V265MOHM45V25V122A81A20V163W103NC10V51NC45V25VB; DRAWING: #NAME?; MAX_CURRENT: 81A; MAX_VOLTAGE: 30V; MAX_WATTAGE: 1.63W; NV_NAME: NTTFS4C25N; NV_PN: 300-1021-000; PACK_TYPE: DFN3X3; PATH: I23; PHYS_PAGE: 8; Q_G: 10.3nC@10V / 5.1nC@4.5V / [ ]@2.5V; ROT: 0; R_DS_ON: 17mohm@10V / 26.5mohm@4.5V / [ ]@2.5V; SEC: 1; VER: 5; V_BE_GS: 20V; XY: (-6550,4600)
Q5 = Q_FET_N_ENH#2: ASSEMBLY: PS_5V; CDS_LIB: discrete; CDS_PART_NAME: Q_FET_N_ENH_DFN3X3-NTTFS4C06NTAG,30V,4.2MOHM@10V / 6.1MOHM@4.5V / [ ]@2.5V,18A,166A,20V,2.16W,26NC@10V / 11.6NC@4.5V / [ ]@2.5A; CDS_PHYS_PART_NAME: Q_FET_N_ENH_DFN3X3-NTTFS4C06NTAG,30V,4.2MOHM@10V / 6.1MOHM@4.5V / [ ]@2.5V,18A,166A,20V,2.16W,26NC@10V / 11.6NC@4.5V / [ ]@2.5B; CDS_SEC: 1; CONTINUOUS_CURRENT: 18A; DEVICE_TYPENAME: Q_FET_N_ENH_DFN3X3-NTTFS4C06NTAG30V42MOHM10V61MOHM45V25V18A166A20V216W26NC10V116NC45V25B; DRAWING: #NAME?; MAX_CURRENT: 166A; MAX_VOLTAGE: 30V; MAX_WATTAGE: 2.16W; NV_NAME: NTTFS4C06NTAG; NV_PN: 300-0284-000; PACK_TYPE: DFN3X3; PATH: I1; PHYS_PAGE: 8; Q_G: 26nC@10V / 11.6nC@4.5V / [ ]@2.5V; ROT: 0; R_DS_ON: 4.2mohm@10V / 6.1mohm@4.5V / [ ]@2.5V; SEC: 1; VER: 5; V_BE_GS: 20V; XY: (-6550,3900)
R14 = R#1: ASSEMBLY: PS_5V; CDS_LIB: discrete; CDS_PART_NAME: R_0402-10K,1 %,62.5MW,195-0004-000; CDS_PHYS_PART_NAME: R_0402-10K,1 %,62.5MW,195-0004-000-10K,195-0004-000; CDS_SEC: 1; CHIPS_PART_NAME: R; DEVICE_TYPENAME: R_0402-10K1625MW195-0004-000-10K195-0004-000; DRAWING: #NAME?; MAX_WATTAGE: 62.5mW; NV_PN: 195-0004-000; PATH: I39; PHYS_PAGE: 8; ROT: 0; SEC: 1; SIGNAL_MODEL: nv_res; TOL: 1%; VER: 1; XY: (-9400,4400)
R15 = R#1: ASSEMBLY: PS_5V; CDS_LIB: discrete; CDS_PART_NAME: R_0402-0OHM,0.05 OHM,62.5MW,195-2655-000; CDS_PHYS_PART_NAME: R_0402-0OHM,0.05 OHM,62.5MW,195-2655-000-0OHM,195-2655-000; CDS_SEC: 1; CHIPS_PART_NAME: R; DEVICE_TYPENAME: R_0402-0OHM005OHM625MW195-2655-000-0OHM195-2655-000; DRAWING: #NAME?; MAX_WATTAGE: 62.5mW; NV_PN: 195-2655-000; PATH: I31; PHYS_PAGE: 8; ROT: 0; SEC: 1; TOL: 0.05 ohm; VER: 1; XY: (-7650,4600)
R16 = R: ASSEMBLY: PS_5V; CDS_LIB: discrete; CDS_PART_NAME: R_0805-3.3OHM,5 %,0.125W,195-1602-000; CDS_PHYS_PART_NAME: R_0805-3.3OHM,5 %,0.125W,195-1602-000-195-1602-000,3.3OHM; CDS_SEC: 1; DEVICE_TYPENAME: R_0805-33OHM50125W195-1602-000-195-1602-00033OHM; DRAWING: #NAME?; MAX_WATTAGE: 0.125W; NV_PN: 195-1602-000; PATH: I27; PHYS_PAGE: 8; ROT: 0; SEC: 1; SIGNAL_MODEL: nv_res; TOL: 5%; VER: 2; XY: (-7400,3650)
R17 = R: ASSEMBLY: PS_5V; CDS_LIB: discrete; CDS_PART_NAME: R_0402-18.2K,1 %,62.5MW,195-0130-000; CDS_PHYS_PART_NAME: R_0402-18.2K,1 %,62.5MW,195-0130-000-18.2K,195-0130-000; CDS_SEC: 1; DEVICE_TYPENAME: R_0402-182K1625MW195-0130-000-182K195-0130-000; DRAWING: #NAME?; MAX_WATTAGE: 62.5mW; NV_PN: 195-0130-000; PATH: I26; PHYS_PAGE: 8; ROT: 0; SEC: 1; SIGNAL_MODEL: nv_res; TOL: 1%; VER: 2; XY: (-7000,3450)
R18 = R: ASSEMBLY: PS_5V; CDS_LIB: discrete; CDS_PART_NAME: R_0402-100OHM,1 %,62.5MW,195-0002-000; CDS_PHYS_PART_NAME: R_0402-100OHM,1 %,62.5MW,195-0002-000-100OHM,195-0002-000; CDS_SEC: 1; DEVICE_TYPENAME: R_0402-100OHM1625MW195-0002-000-100OHM195-0002-000; DRAWING: #NAME?; MAX_WATTAGE: 62.5mW; NV_PN: 195-0002-000; PATH: I17; PHYS_PAGE: 8; ROT: 0; SEC: 1; SIGNAL_MODEL: nv_res; TOL: 1%; VER: 2; XY: (-4600,3900)
R19 = R: ASSEMBLY: PS_5V; CDS_LIB: discrete; CDS_PART_NAME: R_0402-124K,1 %,62.5MW,195-0051-000; CDS_PHYS_PART_NAME: R_0402-124K,1 %,62.5MW,195-0056-000-127K,195-0051-000; CDS_SEC: 1; DEVICE_TYPENAME: R_0402-127K1625MW195-0056-000-127K195-0056-000; DRAWING: #NAME?; MAX_WATTAGE: 62.5mW; NV_PN: 195-0051-000; PATH: I18; PHYS_PAGE: 8; ROT: 0; SEC: 1; TOL: 1%; VER: 2; XY: (-4600,3250)
R20 = R: ASSEMBLY: PS_5V; CDS_LIB: discrete; CDS_PART_NAME: R_0402-22.1K,1 %,62.5MW,195-0170-000; CDS_PHYS_PART_NAME: R_0402-22.1K,1 %,62.5MW,195-0170-000-195-0170-000,22.1K; CDS_SEC: 1; DEVICE_TYPENAME: R_0402-221K1625MW195-0170-000-195-0170-000221K; DRAWING: #NAME?; MAX_WATTAGE: 62.5mW; NV_PN: 195-0170-000; PATH: I34; PHYS_PAGE: 8; ROT: 0; SEC: 1; SIGNAL_MODEL: DEFAULT_RESISTOR_649OHM_2_1; TOL: 1%; VER: 2; XY: (-4600,2700)
R21 = R: ASSEMBLY: PS_5V; CDS_LIB: discrete; CDS_PART_NAME: R_0402-47.5K,1 %,62.5MW,195-0330-000; CDS_PHYS_PART_NAME: R_0402-47.5K,1 %,62.5MW,195-0330-000-195-0330-000,47.5K; CDS_SEC: 1; DEVICE_TYPENAME: R_0402-475K1625MW195-0330-000-195-0330-000475K; DRAWING: #NAME?; MAX_WATTAGE: 62.5mW; NV_PN: 195-0330-000; PATH: I14; PHYS_PAGE: 8; ROT: 0; SEC: 1; SIGNAL_MODEL: nv_res; TOL: 1%; VER: 2; XY: (-4250,3350)
R163 = R: ASSEMBLY: PS_5V; CDS_LIB: discrete; CDS_PART_NAME: R_0402-10K,1 %,62.5MW,195-0004-000; CDS_PHYS_PART_NAME: R_0402-10K,1 %,62.5MW,195-0004-000-10K,195-0004-000; CDS_SEC: 1; DEVICE_TYPENAME: R_0402-10K1625MW195-0004-000-10K195-0004-000; DRAWING: #NAME?; MAX_WATTAGE: 62.5mW; NV_PN: 195-0004-000; PATH: I47; PHYS_PAGE: 8; ROT: 0; SEC: 1; SIGNAL_MODEL: nv_res; TOL: 1%; VER: 2; XY: (-1700,2950)
U3 = U_SWREG_TPS53015: ASSEMBLY: PS_5V; CDS_LIB: power_supply; CDS_PART_NAME: U_SWREG_TPS53015_XSOP10-TPS53015,BUCK,1PH,500KHZ,NONE,0.77V..7V,1%,0.773V,28V,10A,50W,316-0314-000; CDS_PHYS_PART_NAME: U_SWREG_TPS53015_XSOP10-TPS53015,BUCK,1PH,500KHZ,NONE,0.77V..7V,1%,0.773V,28V,10A,50W,316-0314-000-0.773V,316-0314-000; CDS_SEC: 1; DEVICE_TYPENAME: U_SWREG_TPS53015_XSOP10-TPS53015BUCK1PH500KHZNONE077V7V10773V28V10A50W316-0314-000-0773V316-0314-000; DRAWING: #NAME?; MAX_CURRENT: 10A; MAX_VOLTAGE: 28V; MAX_WATTAGE: 50W; MODE: Buck; NV_NAME: TPS53015; NV_PN: 316-0314-000; OUTPUT_VOLTAGE: 0.77V..7V; PACK_TYPE: XSOP10; PATH: I33; PHASES: 1Ph; PHYS_PAGE: 8; PROGRAMMABLE: None; ROT: 0; SEC: 1; SWITCHING_FREQ: 500KHz; TOL: 1%; VER: 1; XY: (-8250,4050)

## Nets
GND: C6.2 C7.2 C8.2 C9.2 C10.2 C11.2 C15.2 C16.2 C143.2 C148.2 C149.2 C152.2 C153.2 C154.2 C171.2 D64.2 D65.2(A) J16.2 J16.3 J18.2 Q5.1(S1) Q5.2(S2) Q5.3(S3) R17.2 R20.2 R173.2 R182.2 U1.3(GND) U3.6(PGND) U24.3(GND) U24.4(NC1) U24.5(NC2) ; also on sheet 1 2 3 4 5 6 7 8 9 10 11 12 13 14 15 16 21
VDD_1V8: U1.5(VCC) ; also on sheet 2 3 4 5 8 9 15 21
VDD_3V3_SYS: R13.1 ; also on sheet 2 3 4 5 6 7 8 9 12 15 16 20 21
VDD_5V_SYS: C15.1 C16.1 C148.1 C149.1 L3.2 L4.2 R18.1 R163.1 ; also on sheet 2 3 8 9 10 11 12 14 15 16 21
VDD_DCIN: C8.1 C9.1 C11.1 C152.1 C153.1 Q4.5(D) Q25.5(D) R14.2 R172.1 U3.5(VIN) ; also on sheet 14 16
BUCK_5V_BST: R15.1 U3.10(VBST)
BUCK_5V_BST_R: C12.1 R15.2
BUCK_5V_DRVH: Q4.4(G) U3.9(DRVH)
BUCK_5V_DRVL: Q5.4(G) R17.1 U3.7(DRVL)
BUCK_5V_EN: C6.1 R14.1 U3.4(EN)
BUCK_5V_FB: C14.2 R19.2 R20.1 U3.1(VFB)
BUCK_5V_FB_MID: R18.2 R19.1 R21.1
BUCK_5V_FB_MID_R: C14.1 R21.2
BUCK_5V_PG: R163.2 U3.2(PG) ; also on sheet 14 15
BUCK_5V_SNUB: C10.1 R16.2
BUCK_5V_SW: C12.2 L3.1 L4.1 Q4.1(S1) Q4.2(S2) Q4.3(S3) Q5.5(D) R16.1 U3.8(SW)
BUCK_5V_VREG5: C7.1 U3.3(VREG5)
CSI5_CLK_N: J2.76(DSI_A_CLK_N) TP30.1
CSI5_CLK_P: J2.78(DSI_A_CLK_P) TP29.1
CSI5_D0_N: J2.70(DSI_A_D0_N) TP26.1
CSI5_D0_P: J2.72(DSI_A_D0_P) TP25.1
CSI5_D1_N: J2.82(DSI_A_D1_N) TP28.1
CSI5_D1_P: J2.84(DSI_A_D1_P) TP27.1
DCIN_SENSE: C154.1 R172.2 R173.1 U24.2(INPUT)
DCIN_SNUB: C143.1 R171.2
DCJ_IN: C168.1 C171.1 D64.1 D65.1(K) J16.1 J18.1 Q25.1(S1) Q25.2(S2) Q25.3(S3) R171.1 R181.1
DCJ_SS: C168.2 Q25.4(G) R181.2 R182.1
DP0_AUX_N: J2.90(DP_AUX_CH0_N) ; also on sheet 8
DP0_AUX_P: J2.92(DP_AUX_CH0_P) ; also on sheet 8
DP0_HPD: J2.88(DP_HPD) ; also on sheet 8
DP0_TXD0_N: J2.39(EDP_TXD0_N) ; also on sheet 8
DP0_TXD0_P: J2.41(EDP_TXD0_P) ; also on sheet 8
DP0_TXD1_N: J2.45(EDP_TXD1_N) ; also on sheet 8
DP0_TXD1_P: J2.47(EDP_TXD1_P) ; also on sheet 8
DP0_TXD2_N: J2.51(EDP_TXD2_N) ; also on sheet 8
DP0_TXD2_P: J2.53(EDP_TXD2_P) ; also on sheet 8
DP0_TXD3_N: J2.57(EDP_TXD3_N) ; also on sheet 8
DP0_TXD3_P: J2.59(EDP_TXD3_P) ; also on sheet 8
HDMI_CEC: J2.94(HDMI_CEC) ; also on sheet 9
HDMI_DDC_SCL: J2.100(DP_AUX_CH1_P) ; also on sheet 9
HDMI_DDC_SDA: J2.98(DP_AUX_CH1_N) ; also on sheet 9
HDMI_HPD: J2.96(HDMI_INT_DP_HPD) ; also on sheet 9
HDMI_TX0_N: J2.75(HDMI_TXD2_N) ; also on sheet 9
HDMI_TX0_P: J2.77(HDMI_TXD2_P) ; also on sheet 9
HDMI_TX1_N: J2.69(HDMI_TXD1_N) ; also on sheet 9
HDMI_TX1_P: J2.71(HDMI_TXD1_P) ; also on sheet 9
HDMI_TX2_N: J2.63(HDMI_TXD0_N) ; also on sheet 9
HDMI_TX2_P: J2.65(HDMI_TXD0_P) ; also on sheet 9
HDMI_TXC_N: J2.81(HDMI_TXC_N) ; also on sheet 9
HDMI_TXC_P: J2.83(HDMI_TXC_P) ; also on sheet 9
M2E_SUSCLK_32KHZ: R13.2 U1.4(Y) ; also on sheet 5
PCIE0_CLK_N: J2.160(PEX_CLK1_N) ; also on sheet 4
PCIE0_CLK_P: J2.162(PEX_CLK1_P) ; also on sheet 4
PCIE0_CLKREQ: J2.180(PEX_L0_CLKREQ) ; also on sheet 4
PCIE0_RST: J2.181(PEX_L0_RST) ; also on sheet 4
PCIE0_RX0_N: J2.131(PEX_RX4_N) ; also on sheet 4
PCIE0_RX0_P: J2.133(PEX_RX4_P) ; also on sheet 4
PCIE0_RX1_N: J2.137(PEX_RX3_N) ; also on sheet 4
PCIE0_RX1_P: J2.139(PEX_RX3_P) ; also on sheet 4
PCIE0_RX2_N: J2.149(PEX_RX2_N) ; also on sheet 4
PCIE0_RX2_P: J2.151(PEX_RX2_P) ; also on sheet 4
PCIE0_RX3_N: J2.155(PEX_RX1_N) ; also on sheet 4
PCIE0_RX3_P: J2.157(PEX_RX1_P) ; also on sheet 4
PCIE0_TX0_N: J2.134(PEX_TX4_N) ; also on sheet 4
PCIE0_TX0_P: J2.136(PEX_TX4_P) ; also on sheet 4
PCIE0_TX1_N: J2.140(PEX_TX3_N) ; also on sheet 4
PCIE0_TX1_P: J2.142(PEX_TX3_P) ; also on sheet 4
PCIE0_TX2_N: J2.148(PEX_TX2_N) ; also on sheet 4
PCIE0_TX2_P: J2.150(PEX_TX2_P) ; also on sheet 4
PCIE0_TX3_N: J2.154(PEX_TX1_N) ; also on sheet 4
PCIE0_TX3_P: J2.156(PEX_TX1_P) ; also on sheet 4
PCIE1_CLK_N: J2.173(PEX_CLK2_N) ; also on sheet 5
PCIE1_CLK_P: J2.175(PEX_CLK2_P) ; also on sheet 5
PCIE1_CLKREQ: J2.182(PEX_L1_CLKREQ) ; also on sheet 5
PCIE1_RST: J2.183(PEX_L1_RST) ; also on sheet 5
PCIE1_RX0_N: J2.167(PEX_RX0_N) ; also on sheet 5
PCIE1_RX0_P: J2.169(PEX_RX0_P) ; also on sheet 5
PCIE1_TX0_N: J2.172(PEX_TX0_N) ; also on sheet 5
PCIE1_TX0_P: J2.174(PEX_TX0_P) ; also on sheet 5
PCIE_WAKE: J2.179(PEX_WAKE) ; also on sheet 4 5
SHUTDOWN_REQ*: U24.1(RST_OUT) ; also on sheet 14 21
SUSCLK_32KHZ: J2.210(CLK_32K_OUT) U1.2(A)
USBSS_RX_N: C5.1 J2.161(PEX_RX6_N)
USBSS_RX_P: C4.1 J2.163(PEX_RX6_P)
USBSS_TX_HUB_N: C5.2 ; also on sheet 12
USBSS_TX_HUB_P: C4.2 ; also on sheet 12
USBSS_TX_N: J2.166(PEX_TX6_N) ; also on sheet 12
USBSS_TX_P: J2.168(PEX_TX6_P) ; also on sheet 12

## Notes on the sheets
sheet 17
- A
- B
- C
- D
- E
- F
- G
- H
- PRE-REG 5V DCDC
- 1
- 1
- 2
- 2
- PCB CO-LAYOUT
- 3
- 3
- ROCL
- Rb1
- Iocl=(Vin-Vout)*Vout/(2*L*fsw*Vin)+Vtrip/Rdson
- Rb2
- take Vin(min) as an
  example
- Vref = 0.773V
- Iocl=(9-5)*5/(2*1*0.5*9)+125/6.1=~22.7A
- Vout = Vref * ((Rb1 / Rb2) + 1)
- Vout = 0.773 * ((127 / 22.1) + 1)=5.21V
- ESTIMATED TOTAL CURRENT
- MODULE = 3A
- 40PIN HDR = 1
- USB = 0.9A (x4) = 3.6A
- 4
- 4
- TOTAL = 7.6A
- 5
- 5
- NVIDIA CORPORATION
- 2701 SAN TOMAS
  EXPRESSWAY
- ASSEMBLY
- <ASSEMBLY_DESCRIPTION>
- SANTA CLARA, CA 95050, USA
- PAGE DETAIL
- PRE-REG 5V
- NV_PN
- 600-13509-BASE-100
- ALL NVIDIA DESIGN SPECIFICATIONS, REFERENCE SPECIFICATIONS, REFERENCE BOARDS, FILES, DRAWINGS, DIAGNOSTICS, LISTS AND OTHER DOCUMENTS OR INFORMATION (TOGETHER AND SEPARATELY, 'MATERIALS') ARE BEING PROVIDED 'AS IS'. THE MATERIALS
  MAY
- CONTAIN KNOWN AND UNKNOWN VIOLATIONS OR DEVIATIONS OF INDUSTRY STANDARDS AND SPECIFICATIONS. NVIDIA MAKES NO WARRANTIES, EXPRESSED, IMPLIED, STATUTORY OR OTHERWISE WITH RESPECT TO THE MATERIALS OR OTHERWISE, AND EXPRESSLY DISCLAIMS
  ALL
- PCB REV
- P3509-A01
- PAGE
- 8 OF 25
- IMPLIED WARRANTIES INCLUDING, WITHOUT LIMITATION, THE WARRANTIES OF DESIGN, OF NONINFRINGEMENT, MERCHANTABILITY OR FITNESS FOR A PARTICULAR PURPOSE, OR ARISING FROM A COURSE OF DEALING, TRADE USAGE, TRADE PRACTICE, OR INDUSTRY
  STANDARDS.
- BOM REV
- <BOM_REV>
- DATE
- 27-NOV-2019
- A
- B
- C
- D
- E
- F
- G
- H
sheet 18
- A
- B
- C
- D
- E
- F
- G
- H
- DC JACK POWER PATH
- 1
- 1
- RESERVED FOR POE
- BACKPOWER
- 2
- 2
- 3
- 3
- 4
- 4
- 5
- 5
- NVIDIA CORPORATION
- 2701 SAN TOMAS
  EXPRESSWAY
- ASSEMBLY
- <ASSEMBLY_DESCRIPTION>
- SANTA CLARA, CA 95050, USA
- PAGE DETAIL
- DC_JACK
- NV_PN
- 600-13509-BASE-100
- ALL NVIDIA DESIGN SPECIFICATIONS, REFERENCE SPECIFICATIONS, REFERENCE BOARDS, FILES, DRAWINGS, DIAGNOSTICS, LISTS AND OTHER DOCUMENTS OR INFORMATION (TOGETHER AND SEPARATELY, 'MATERIALS') ARE BEING PROVIDED 'AS IS'. THE MATERIALS
  MAY
- CONTAIN KNOWN AND UNKNOWN VIOLATIONS OR DEVIATIONS OF INDUSTRY STANDARDS AND SPECIFICATIONS. NVIDIA MAKES NO WARRANTIES, EXPRESSED, IMPLIED, STATUTORY OR OTHERWISE WITH RESPECT TO THE MATERIALS OR OTHERWISE, AND EXPRESSLY DISCLAIMS
  ALL
- PCB REV
- P3509-A01
- PAGE
- 7 OF 25
- IMPLIED WARRANTIES INCLUDING, WITHOUT LIMITATION, THE WARRANTIES OF DESIGN, OF NONINFRINGEMENT, MERCHANTABILITY OR FITNESS FOR A PARTICULAR PURPOSE, OR ARISING FROM A COURSE OF DEALING, TRADE USAGE, TRADE PRACTICE, OR INDUSTRY
  STANDARDS.
- BOM REV
- <BOM_REV>
- DATE
- 27-NOV-2019
- A
- B
- C
- D
- E
- F
- G
- H
sheet 19
- A
- B
- C
- D
- E
- F
- G
- H
- CSI (contn'd), HDMI, DP, DSI, USBSS and PCIE
- 1
- 1
- TESTPOINT
- nvme
- 2
- 2
- DP Con
- 3
- 3
- HDMI Con
- USB Type-A Con (USBSS)
- M.2 key e wifi/bt
- 4
- 4
- 5
- 5
- NVIDIA CORPORATION
- 2701 SAN TOMAS EXPRESSWAY
- ASSEMBLY
- <ASSEMBLY_DESCRIPTION>
- SANTA CLARA, CA 95050, USA
- PAGE DETAIL
- SODIMM Connector 3/3
- NV_PN
- 600-13509-BASE-100
- ALL NVIDIA DESIGN SPECIFICATIONS, REFERENCE SPECIFICATIONS, REFERENCE BOARDS, FILES, DRAWINGS, DIAGNOSTICS, LISTS AND OTHER DOCUMENTS OR INFORMATION (TOGETHER AND SEPARATELY, 'MATERIALS') ARE BEING PROVIDED 'AS IS'. THE MATERIALS MAY
- CONTAIN KNOWN AND UNKNOWN VIOLATIONS OR DEVIATIONS OF INDUSTRY STANDARDS AND SPECIFICATIONS. NVIDIA MAKES NO WARRANTIES, EXPRESSED, IMPLIED, STATUTORY OR OTHERWISE WITH RESPECT TO THE MATERIALS OR OTHERWISE, AND EXPRESSLY DISCLAIMS ALL
- PCB REV
- P3509-A01
- PAGE
- 6 OF 25
- IMPLIED WARRANTIES INCLUDING, WITHOUT LIMITATION, THE WARRANTIES OF DESIGN, OF NONINFRINGEMENT, MERCHANTABILITY OR FITNESS FOR A PARTICULAR PURPOSE, OR ARISING FROM A COURSE OF DEALING, TRADE USAGE, TRADE PRACTICE, OR INDUSTRY STANDARDS.
- BOM REV
- <BOM_REV>
- DATE
- 27-NOV-2019
- A
- B
- C
- D
- E
- F
- G
- H
